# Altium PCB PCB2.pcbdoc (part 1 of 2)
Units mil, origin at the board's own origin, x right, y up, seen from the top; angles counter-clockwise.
Board outline 1825.45 x 2756.54 mil, 4 copper layers (Top Layer, 3.3V, GND, Bottom Layer); 87 components, 95 nets, 418 pads, 113 vias.
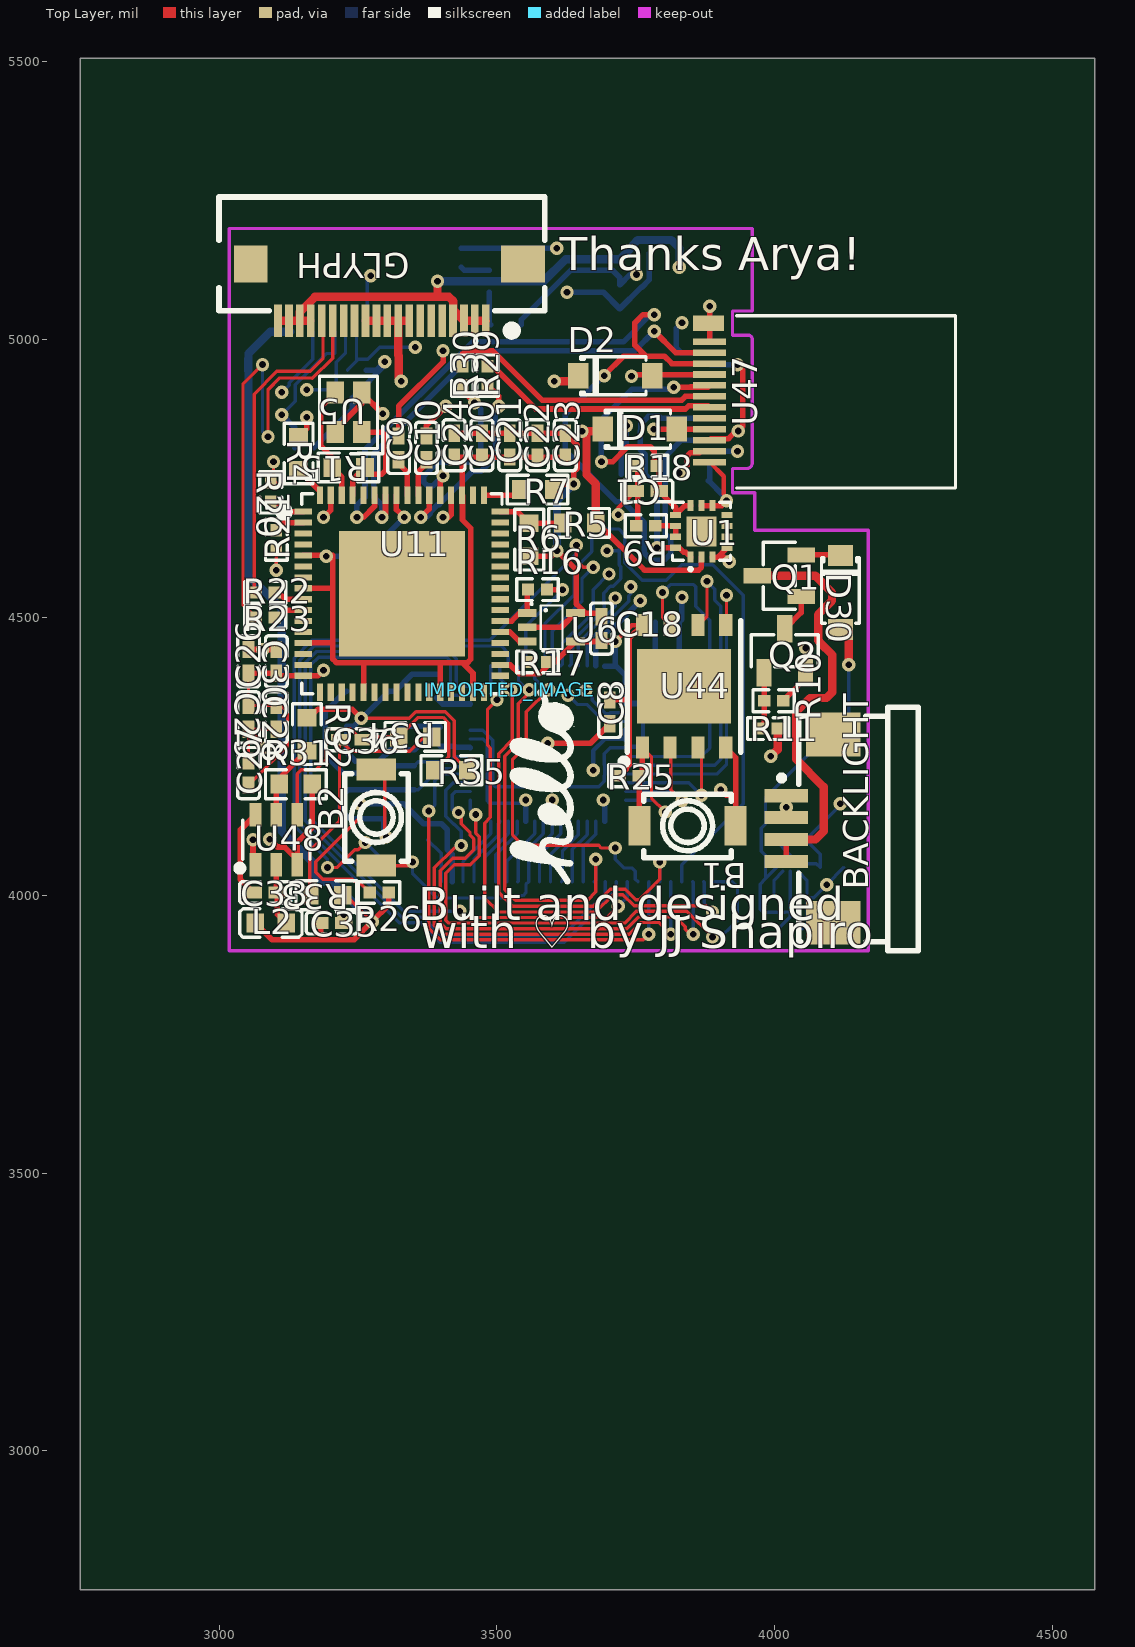
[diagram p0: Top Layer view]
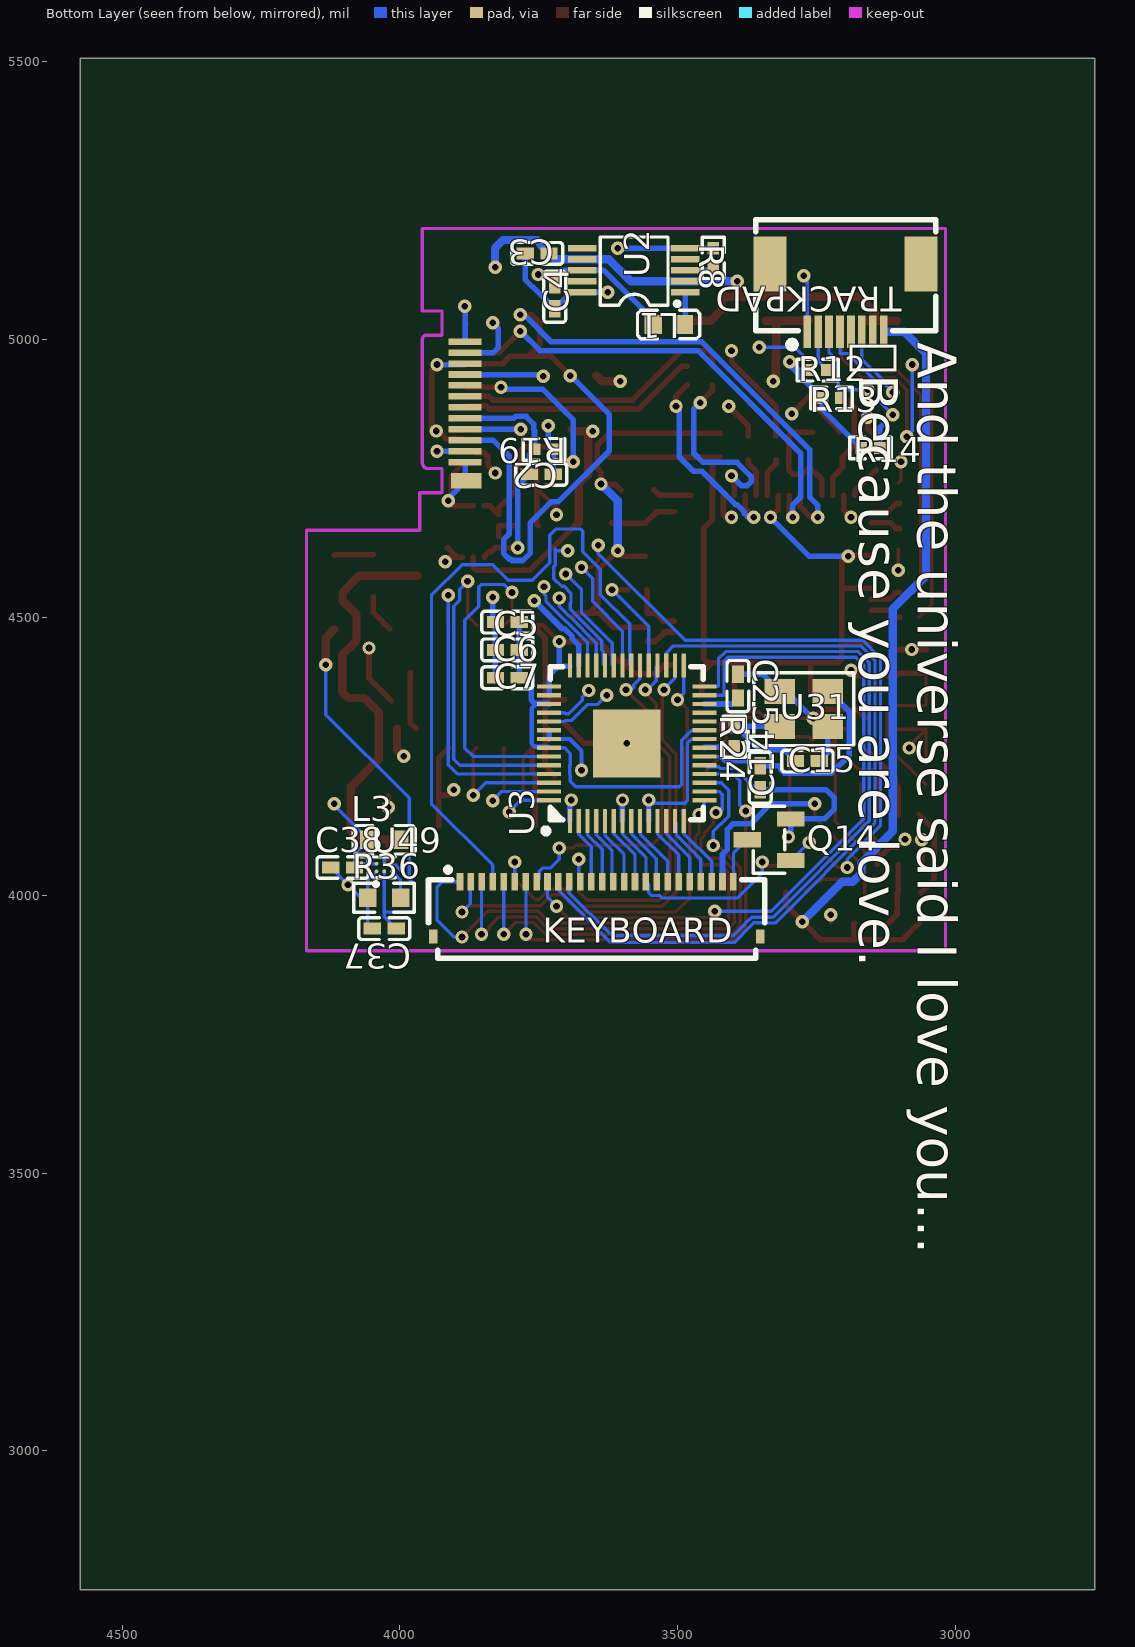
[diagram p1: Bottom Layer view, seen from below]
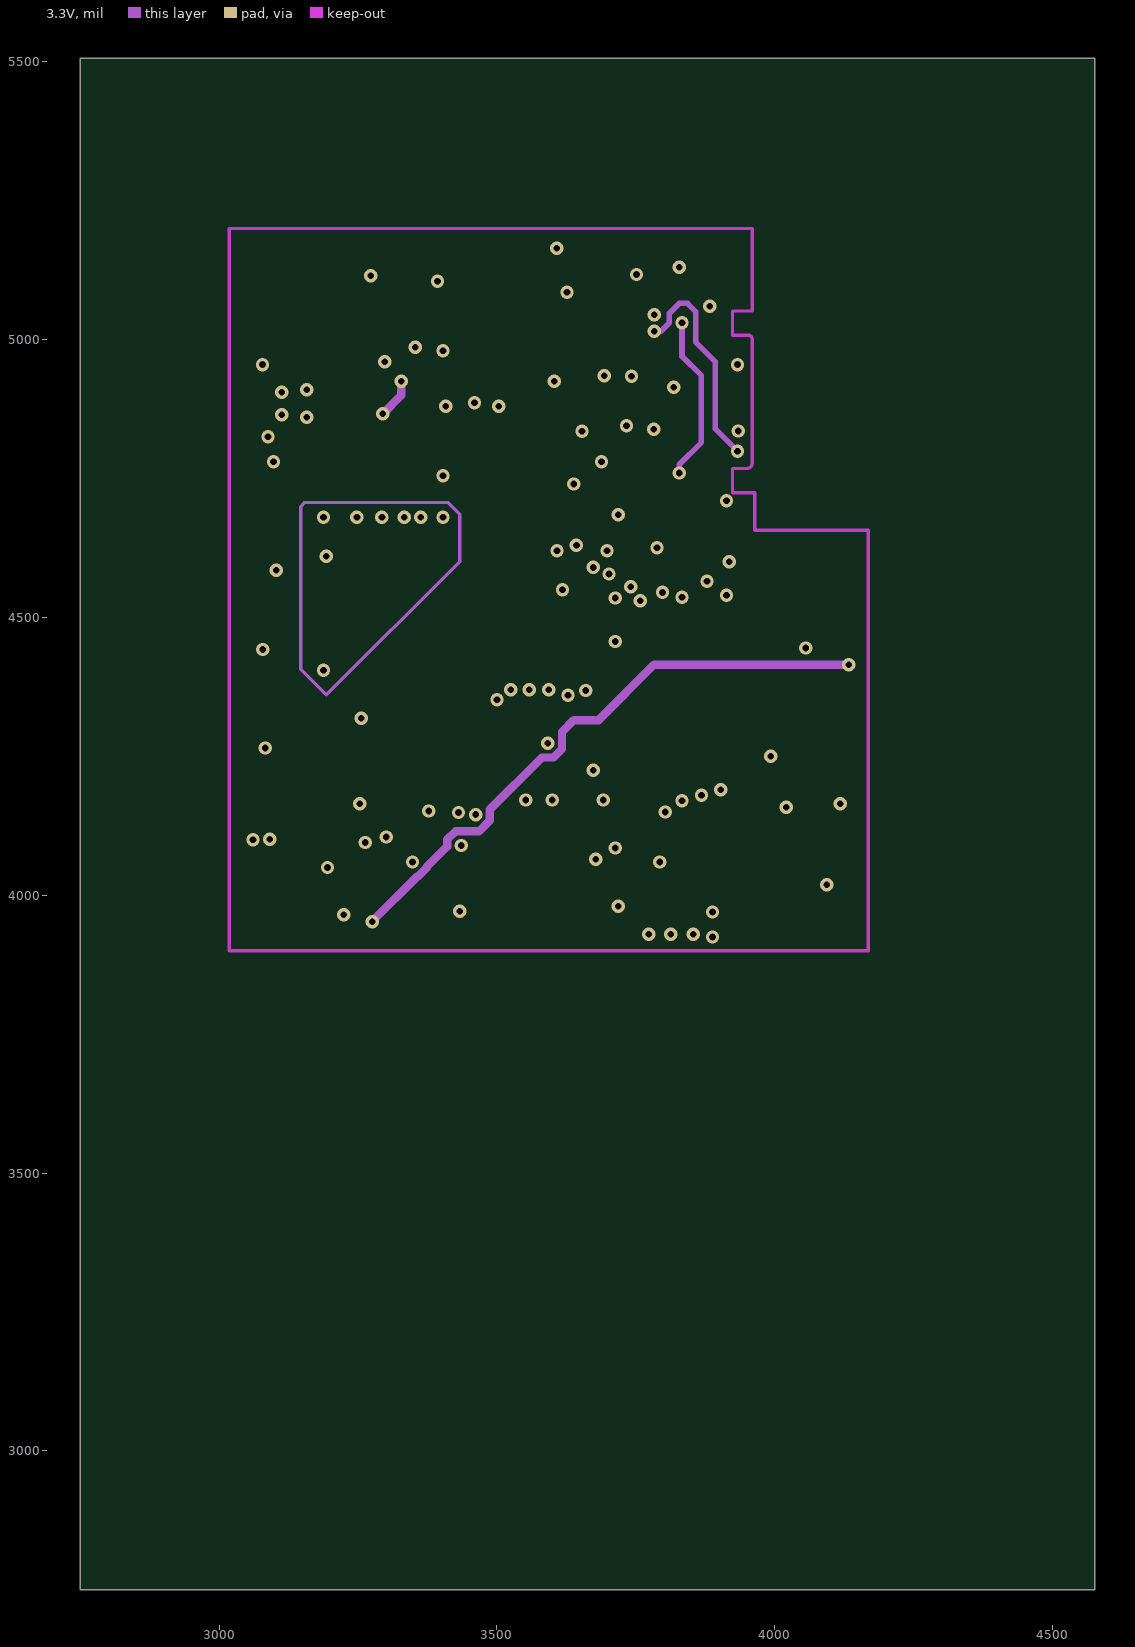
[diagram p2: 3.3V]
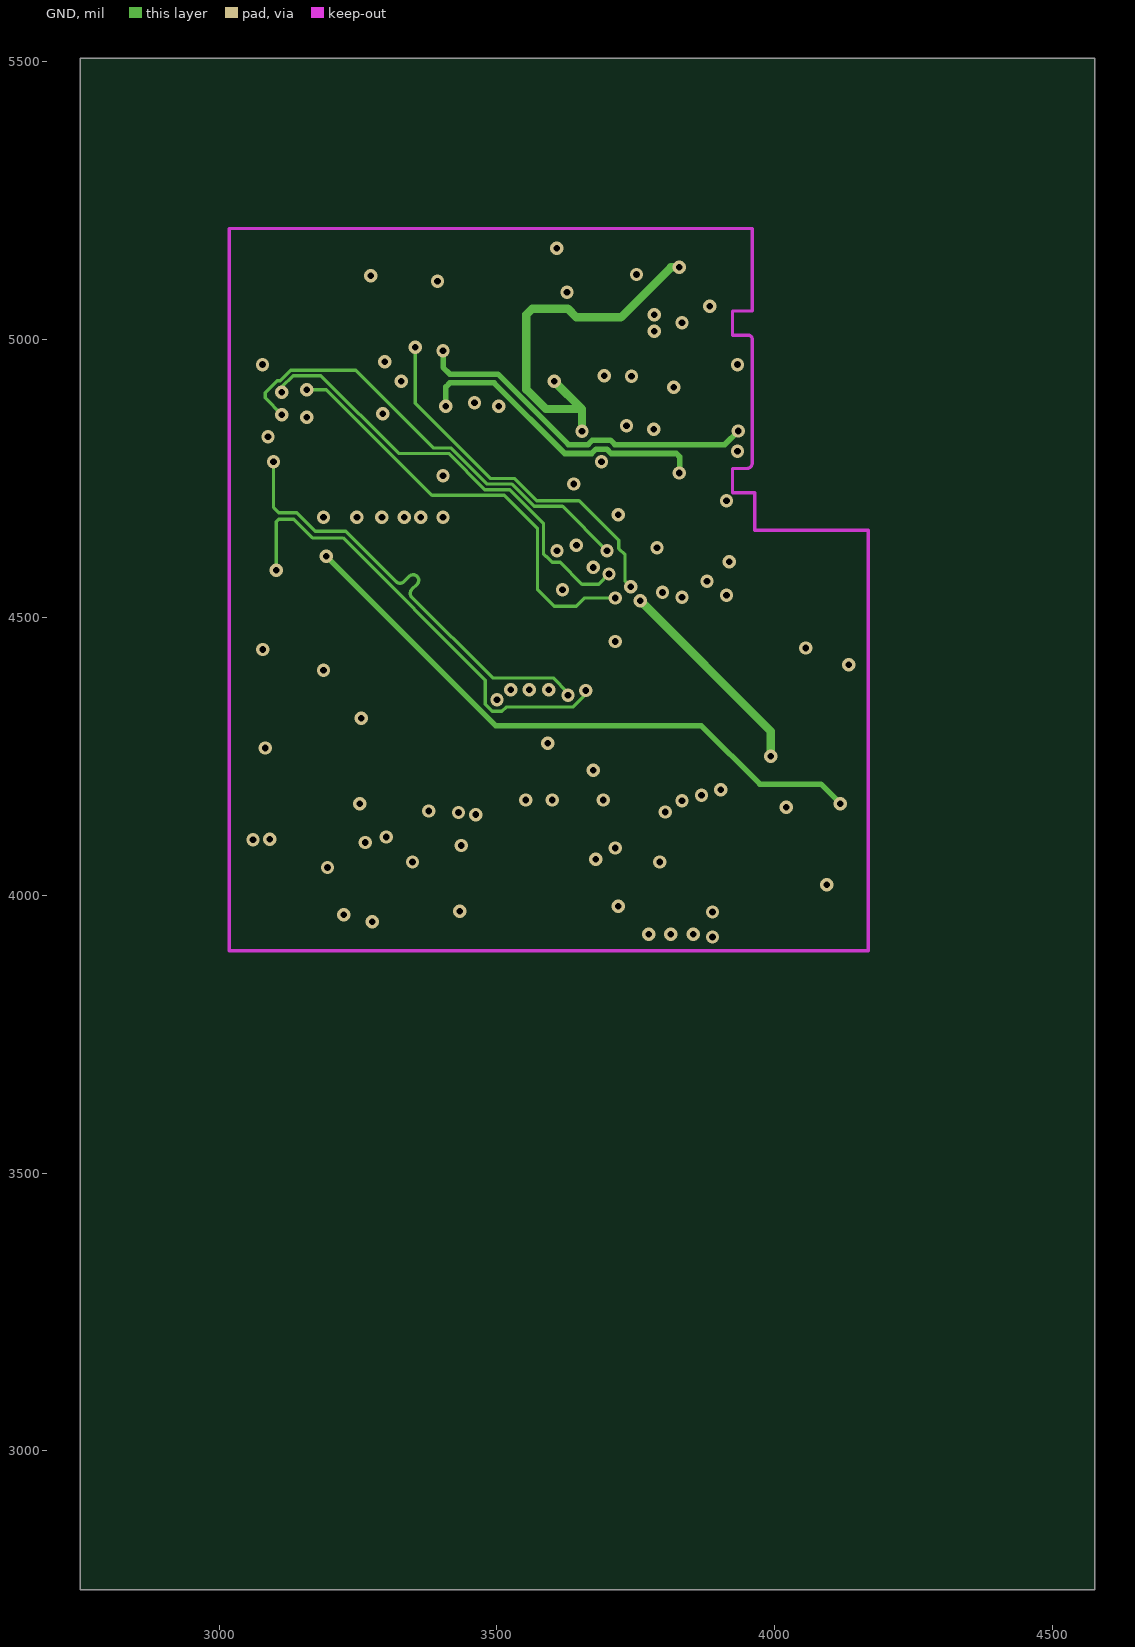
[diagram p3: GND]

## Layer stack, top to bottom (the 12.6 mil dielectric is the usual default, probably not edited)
Top Layer: signal copper (thickness not stored)
Dielectric: dielectric 12.6, FR-4, Dk 4.8
3.3V: signal copper (thickness not stored)
Dielectric: dielectric 12.6, FR-4, Dk 4.8
GND: signal copper (thickness not stored)
Dielectric: dielectric 12.6, FR-4, Dk 4.8
Bottom Layer: signal copper (thickness not stored)

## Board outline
4575.45,2750 2750,2750 2750,5506.54 4575.45,5506.54

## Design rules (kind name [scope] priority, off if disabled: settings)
BoardOutlineClearance copperThickness1oz [All] p0: genericclearance=10 ignorepadtopadclearanceinfootprint=FALSE except(0: Arc-SplitContinuation Track-SplitContinuation SMDPad-SplitContinuation THPad-SplitContinuation Via-SplitContinuation Fill-SplitContinuation Poly-SplitContinuation Region-SplitContinuation Text-SplitContinuation; 6: Track-CutoutEdge SMDPad-CutoutEdge THPad-CutoutEdge Via-CutoutEdge Region-CutoutEdge; 11.8: Track-OutlineEdge SMDPad-OutlineEdge THPad-OutlineEdge Via-OutlineEdge Fill-OutlineEdge Region-OutlineEdge Poly-OutlineEdge Text-OutlineEdge Fill-CutoutEdge)
BoardOutlineClearance copperThickness2oz [All] p0: genericclearance=10 ignorepadtopadclearanceinfootprint=FALSE except(0: Arc-SplitContinuation Track-SplitContinuation SMDPad-SplitContinuation THPad-SplitContinuation Via-SplitContinuation Fill-SplitContinuation Poly-SplitContinuation Region-SplitContinuation Text-SplitContinuation; 6: Track-CutoutEdge SMDPad-CutoutEdge THPad-CutoutEdge Via-CutoutEdge Region-CutoutEdge; 11.8: Track-OutlineEdge SMDPad-OutlineEdge THPad-OutlineEdge Via-OutlineEdge Fill-OutlineEdge Region-OutlineEdge Poly-OutlineEdge Text-OutlineEdge Fill-CutoutEdge)
Clearance copperThickness1oz [(InNet('GND') OR InNet('QSPI_SS') OR InNet('KBRD19') OR InNet('BACKLIGHT+') OR InNet('CC1') OR InNet('CC2') OR InNet('VBUS') OR InNet('+3.3V') OR InNet('$1N20') OR InNet('$1N39') OR InNet('SSTXN1') OR InNet('$1N41') OR InNet('SSTXP1') OR InNet('$1N24') OR InNet('$1N25') OR InNet('1.1V') OR InNet('$1N47') OR InNet('$1N84') OR InNet('$1N83') OR InNet('+5V') OR InNet('$1N2257') OR InNet('EINK_OLED_USB_M') OR InNet('EINK_OLED_USB_P') OR InNet('KBRD0') OR InNet('KBRD1') OR InNet('KBRD2') OR InNet('KBRD3') OR InNet('KBRD4') OR InNet('KBRD5') OR InNet('KBRD6') OR InNet('KBRD7') OR InNet('KBRD8') OR InNet('KBRD9') OR InNet('KBRD10') OR InNet('KBRD11') OR InNet('KBRD12') OR InNet('KBRD13') OR InNet('KBRD14') OR InNet('KBRD15') OR InNet('KBRD16') OR InNet('KBRD18') OR InNet('KBRD17') OR InNet('KBRD20') OR InNet('KBRD21') OR InNet('KBRD22') OR InNet('KBRD23') OR InNet('$1N22') OR InNet('CAPS-') OR InNet('$1N10') OR InNet('$1N27') OR InNet('$1N26') OR InNet('$1N19') OR InNet('$1N2') OR InNet('$1N1') OR InNet('$1N2142') OR InNet('$1N14') OR InNet('$1N15') OR InNet('KBRD_CTRL') OR InNet('TOUCHPAD_INT') OR InNet('TOUCHPAD_SCL') OR InNet('TOUCHPAD_SDA') OR InNet('$1N37') OR InNet('$1N36') OR InNet('$1N73') OR InNet('$1N72') OR InNet('$1N2151') OR InNet('KBRDUSB_P') OR InNet('$1N2152') OR InNet('KBRDUSB_M') OR InNet('$1N2157') OR InNet('$1N2158') OR InNet('$1N2308') OR InNet('TOUCHPAD_ID') OR InNet('INT_USBC_CTRL') OR InNet('SCL_USBC_CTRL') OR InNet('SDA_USBC_CTRL') OR InNet('QSPI_SD3') OR InNet('QSPI_SCLK') OR InNet('QSPI_SD0') OR InNet('QSPI_SD2') OR InNet('QSPI_SD1') OR InNet('SSRXN1') OR InNet('SSRXP1') OR InNet('USB_UP-') OR InNet('USB_UP+') OR InNet('$1N27720') OR InNet('$1N27715') OR InNet('$1N27575') OR InNet('$1N49028') OR InNet('$1N49024') OR InNet('$1N49243') OR InNet('$1N49255') OR InNet('$1N48925') OR InNet('$1N58950') OR InNet('$1N59042'))] p1: gap=7 ignorepadtopadclearanceinfootprint=FALSE except(4: Track-Track; 6: Track-SMDPad SMDPad-SMDPad Track-THPad SMDPad-THPad THPad-THPad Track-Via SMDPad-Via THPad-Via Via-Via SMDPad-Fill THPad-Fill Via-Fill Fill-Fill Track-Region SMDPad-Region THPad-Region Via-Region Region-Region Track-Poly SMDPad-Poly THPad-Poly Via-Poly Fill-Poly Region-Poly Poly-Poly Track-Text SMDPad-Text THPad-Text Via-Text Fill-Text Region-Text Poly-Text Text-Text; 6.9: Track-Hole SMDPad-Hole THPad-Hole Via-Hole Fill-Hole Region-Hole Poly-Hole Text-Hole Sheet-Hole; 11.8: Track-Fill Fill-Region Track-Sheet SMDPad-Sheet THPad-Sheet Via-Sheet Fill-Sheet Region-Sheet Poly-Sheet Text-Sheet)
Clearance copperThickness2oz [All] p1: gap=7 ignorepadtopadclearanceinfootprint=FALSE except(6: Track-SMDPad SMDPad-SMDPad Track-THPad SMDPad-THPad THPad-THPad Track-Via SMDPad-Via THPad-Via Via-Via SMDPad-Fill THPad-Fill Via-Fill Fill-Fill Track-Region SMDPad-Region THPad-Region Via-Region Region-Region Track-Poly SMDPad-Poly THPad-Poly Via-Poly Fill-Poly Region-Poly Poly-Poly Track-Text SMDPad-Text THPad-Text Via-Text Fill-Text Region-Text Poly-Text Text-Text; 6.9: Track-Hole SMDPad-Hole THPad-Hole Via-Hole Fill-Hole Region-Hole Poly-Hole Text-Hole Sheet-Hole; 8: Track-Track; 11.8: Track-Fill Fill-Region Track-Sheet SMDPad-Sheet THPad-Sheet Via-Sheet Fill-Sheet Region-Sheet Poly-Sheet Text-Sheet)
DiffPairsRouting differentialPair [All] p1: maxuncoupledlength=10 minlimit=6 maxlimit=6 mostfreqgap=6 toplayer_minwidth=5 toplayer_prefwidth=10 toplayer_maxwidth=100 bottomlayer_minwidth=5 bottomlayer_prefwidth=10 bottomlayer_maxwidth=100 midlayer1_minwidth=5 midlayer1_prefwidth=10 midlayer1_maxwidth=100 midlayer2_minwidth=5 midlayer2_prefwidth=10 midlayer2_maxwidth=100
PasteMaskExpansion pasteMaskExpansion [All] p1: expansion=0
PlaneConnect innerPlane [All] p1: planeconnectstyle=Relief reliefexpansion=20 reliefentries=4 reliefconductorwidth=10 reliefairgap=10
PolygonConnect copperRegion [All] p1: connectstyle=Relief reliefentries=4 reliefconductorwidth=10 polygonreliefangle="90 Angle" airgapwidth=10
RoutingVias viaSize [All] p1: viastyle="Through Hole" holewidth=12.0078 minholewidth=11.811 maxholewidth=248.0314 width=24.0158 minwidth=19.685 maxwidth=393.7008
SolderMaskExpansion solderMaskExpansion [All] p1: useseparateexpansions=TRUE expansion=2 expansionbottom=2
Width copperThickness1oz [All] p1: maxlimit=100 minlimit=5 preferedwidth=10
Width copperThickness2oz [All] p1: maxlimit=100 minlimit=8 preferedwidth=10

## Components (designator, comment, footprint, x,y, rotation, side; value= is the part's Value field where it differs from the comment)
B1 "BUTTON" SW-SMD_L3.9-W2.9-LS4.9-L 3843.15,4125 r180 top
B2 "BUTTON" SW-SMD_L3.9-W2.9-LS4.9-L 3283.15,4140 r90 top
BACKLIGHT "FPC-1.0-4P" FPC-SMD_4P-P1.00_HDGC_1.0K-ES-4PWB 4063.15,4120 r90 top
C1 "400pF" C0402 3770.65,4727.5 r180 top
C2 "400pF" C0402 3745.65,4757.5 r0 bottom
C3 "1uF" C0402 3753.15,5155 r180 bottom
C4 "10uF" C0402 3721.17,5076.98 r270 bottom
C5 "470nF" C0402 3806.61,4491.53 r180 bottom
C6 "470nF" C0402 3806.61,4441.53 r180 bottom
C7 "470nF" C0402 3806.61,4391.53 r180 bottom
C8 "0.1uF" C0402 3703.15,4330 r90 top
C9 "0.1uF" C0402 3323.15,4805 r90 top
C10 "0.1uF" C0402 3373.15,4805 r90 top
C14 "15pF" C0402 3351.61,4211.53 r270 bottom
C15 "15pF" C0402 3266.61,4241.53 r180 bottom
C18 "0.1uF" C0402 3688.15,4480 r270 top
C20 "0.1uF" C0402 3473.15,4810 r90 top
C21 "0.1uF" C0402 3523.15,4810 r90 top
C22 "0.1uF" C0402 3573.15,4810 r90 top
C23 "0.1uF" C0402 3623.15,4810 r90 top
C24 "10uF" C0402 3423.15,4810 r90 top
C25 "0.1uF" C0402 3391.61,4376.53 r270 bottom
C26 "10uF" C0402 3103.15,4420.81 r90 top
C27 "0.1uF" C0402 3053.15,4220 r90 top
C28 "0.1uF" C0402 3103.15,4320 r270 top
C29 "0.1uF" C0402 3053.15,4320 r270 top
C30 "0.1uF" C0402 3053.15,4420.81 r90 top
C33 "0.1uF" C0402 3083.15,4005 r180 top
C35 "10uF" C0402 3203.15,3950 r0 top
C36 "75pF" C0402 3238.15,4280 r0 top
C37 "4.7uF" C0402 4028.15,3940 r0 bottom
C38 "10uF" C0402 4103.15,4050 r180 bottom
D1 "1N4007W" SOD-123_L2.8-W1.8-LS3.7-RD 3757.18,4838.79 r0 top
D2 "1N4007W" SOD-123_L2.8-W1.8-LS3.7-RD 3713.15,4935 r0 top
D30 "1N4007W" SOD-123_L2.8-W1.8-LS3.7-RD 4118.15,4545 r270 top
GLYPH "HC-FPC-0.5-20P-FH20" FPC-SMD_20P-P0.50_HC-FPC-0.5-20P-FH20 3293.15,5085 r180 top
IMPORTED_IMAGE "IMPORTED_IMAGE" IMPORTED_IMAGE 3523.15,4370 r0 top
KEYBOARD "046809626210846+" FPC-SMD_26P-P0.50_046809626210846 3645.75,3975 r180 bottom
L1 "47uH" L0603 3516.17,5026.98 r0 bottom
L2 "47uH" L0603 3093.15,3950 r0 top
L3 "47uH" L0603 4028.15,4100 r180 bottom
Q1 "CJ2305" SOT-23-3_L2.9-W1.3-P1.90-LS2.4-BR 4008.15,4575 r0 top
Q2 "BC817" SOT-23-3_L2.9-W1.3-P1.90-LS2.4-BR 4018.15,4440 r270 top
Q14 "BC817" SOT-23-3_L2.9-W1.3-P1.90-LS2.4-BR 3335.75,4100 r180 bottom
R4 "9.53k±1%" R0603 3143.15,4795 r270 top
R5 "90.9k±1%" R0603 3648.15,4670 r180 top
R6 "10k±1%" R0603 3558.15,4640 r270 top
R7 "90.9k±1%" R0603 3573.15,4730 r180 top
R8 "56.2k" R0402 3436.17,5146.98 r270 bottom
R9 "5.1k" R0402 3768.15,4665 r180 top
R10 "5.1k" R0402 3998.15,4350 r180 top
R11 "1k" R0402 3988.15,4300 r180 top
R12 "4.7k - 0603" R0402 3248.15,4945 r180 bottom
R13 "4.7k - 0603" R0402 3223.15,4895 r180 bottom
R14 "4.7k" R0402 3153.15,4805 r180 bottom
R15 "1M" R0603 3233.15,4770 r0 top
R16 "4.7k" R0402 3573.15,4550 r0 top
R17 "4.7k" R0402 3573.15,4420 r0 top
R18 "5.1k" R0402 3770.65,4772.5 r0 top
R19 "5.1k" R0402 3740.65,4802.5 r0 bottom
R20 "22" R0402 3093.15,4725 r270 top
R21 "22" R0402 3103.15,4640 r90 top
R22 "22" R0402 3083.15,4545 r0 top
R23 "22" R0402 3083.15,4500 r0 top
R24 "1k" R0402 3398.22,4285.3 r270 bottom
R25 "5.1k" R0402 3738.15,4215 r0 top
R26 "1k" R0402 3288.15,4005 r0 top
R29 "22" R0402 3483.15,4935 r90 top
R30 "22" R0402 3438.15,4935 r90 top
R31 "511k" R0603 3138.15,4200 r0 top
R32 "511k" R0603 3158.15,4290 r270 top
R33 "49.9k" R0603 3193.15,4000 r180 top
R34 "100k" R0603 3353.15,4285 r180 top
R35 "13.3k" R0603 3418.15,4225 r0 top
R36 "36.5" R0603 4028.39,3995.62 r180 bottom
TRACKPAD "TEMPORARY 8-PIN CONN" CONN-SMD_8P-P0.50_HC-FPC-0.5-8P-FHH20 3198.15,5075 r0 bottom
U1 "FUSB302BVMPX" MLP-14_L2.5-W2.5-P0.50-BL-EP 3868.15,4655 r0 top
U2 "LM5165YQDGSRQ1" VSSOP-10_L3.0-W3.0-P0.50-LS4.9-BL 3579.09,5124.61 r90 bottom
U3 "RP2040" LQFN-56_L7.0-W7.0-P0.4-EP 3591.57,4273.38 r90 bottom
U5 "24MHz" OSC-SMD_4P-XRCGB24M000F0L00R0 3233.04,4869 r90 top
U6 "24LC02BT-I/LT" SC-70-5_L2.0-W1.3-P0.65-LS2.1-BR 3598.18,4482.27 r180 top
U11 "TUSB8044ARGCT" VQFN-64_L9.0-W9.0-P0.50-TL-EP5.8 3329.12,4542.65 r0 top
U31 "ABM8-272-T3" CRYSTAL-SMD_4P-L3.2-W2.5-BL-2 3273.22,4335.3 r180 bottom
U44 "W25Q128JVPIM" WSON-8_L5.0-W6.0-P1.27-BL-EP 3836.81,4375.89 r0 top
U47 "TYPE-C 24P-GTJB 040" USB-C-SMD_TYPE-C-24P-GTJB-040 3881.75,4887.9 r90 top
U48 "TPS54302DDCR_C311983" SOT-23-6_L2.9-W1.6-P0.95-LS2.8-BL 3103.15,4100 r0 top
U49 "TPS62801YKAT" DSBGA-6_L1.0-W0.7-R2-C3-P0.35-BL 4028.15,4050 r180 bottom

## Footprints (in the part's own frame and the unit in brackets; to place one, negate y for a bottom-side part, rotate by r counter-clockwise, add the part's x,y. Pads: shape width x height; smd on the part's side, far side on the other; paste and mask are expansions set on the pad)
C0402 [mm]
  rect 0.79x0.54 smd: 1(0.545,0) 2(-0.545,0)
  silkscreen extent -1.17,-0.5 1.17,0.5
CONN-SMD_8P-P0.50_HC-FPC-0.5-8P-FHH20 [mm]
  rect 0.35x1.5 smd: 1(1.75,1.55) 2(1.25,1.55) 3(0.75,1.55) 4(0.25,1.55) 5(-0.25,1.55) 6(-0.75,1.55) 7(-1.25,1.55) 8(-1.75,1.55)
  rect 1.5x2.5 smd: 9(-3.45,-1.55) 10(3.45,-1.55)
  silkscreen extent -4.12,-3.58 4.09,2.44
CRYSTAL-SMD_4P-L3.2-W2.5-BL-2 [mm]
  rect 1.4x1.15 smd: 1(-1.1,-0.8) 2(1.1,-0.8) 3(1.1,0.8) 4(-1.1,0.8)
  silkscreen extent -2.54,-1.9 2.29,1.65
DSBGA-6_L1.0-W0.7-R2-C3-P0.35-BL [mm]
  round 0.17 smd: A1(-0.35,-0.175) A2(-0.35,0.175) B1(0,-0.175) B2(0,0.175) C1(0.35,-0.175) C2(0.35,0.175)
  silkscreen extent -0.5,-0.85 0.5,0.48
FPC-SMD_4P-P1.00_HDGC_1.0K-ES-4PWB [mm]
  rect 0.6x2 smd: 1(1.5,1.075) 2(0.5,1.075) 3(-0.5,1.075) 4(-1.5,1.075)
  rect 2x2.5 smd: 5(-4.3,-1.075) 6(4.3,-1.075)
  silkscreen extent -5.59,-4.95 5.55,1.42
FPC-SMD_20P-P0.50_HC-FPC-0.5-20P-FH20 [mm]
  rect 0.35x1.5 smd: 1(-4.75,1.3) 2(-4.25,1.3) 3(-3.75,1.3) 4(-3.25,1.3) 5(-2.75,1.3) 6(-2.25,1.3) 7(-1.75,1.3) 8(-1.25,1.3) 9(-0.75,1.3) 10(-0.25,1.3) 11(0.25,1.3) 12(0.75,1.3) 13(1.25,1.3) 14(1.75,1.3) 15(2.25,1.3) 16(2.75,1.3) 17(3.25,1.3) 18(3.75,1.3) 19(4.25,1.3) 20(4.75,1.3)
  rect 1.542x1.7 smd: 21(5.992,-1.3)
  rect 2x1.7 smd: 22(-6.45,-1.3)
  silkscreen extent -7.45,-4.36 7.45,2.16
FPC-SMD_26P-P0.50_046809626210846 [mm]
  rect 0.3x0.8 smd: 1(-6.25,1.25) 2(-5.75,1.25) 3(-5.25,1.25) 4(-4.75,1.25) 5(-4.25,1.25) 6(-3.75,1.25) 7(-3.25,1.25) 8(-2.75,1.25) 9(-2.25,1.25) 10(-1.75,1.25) 11(-1.25,1.25) 12(-0.75,1.25) 13(-0.25,1.25) 14(0.25,1.25) 15(0.75,1.25) 16(1.25,1.25) 17(1.75,1.25) 18(2.25,1.25) 19(2.75,1.25) 20(3.25,1.25) 21(3.75,1.25) 22(4.25,1.25) 23(4.75,1.25) 24(5.25,1.25) 25(5.75,1.25) 26(6.25,1.25)
  rect 0.4x0.635 smd: 27(7.475,-1.25) 28(-7.475,-1.25)
  silkscreen extent -7.69,-2.25 7.69,2.03
IMPORTED_IMAGE [mil]
  silkscreen extent 0,-350 116,0
L0603 [mm]
  rect 0.8x0.864 smd: 1(-0.7,0) 2(0.7,0)
  silkscreen extent -1.42,-0.65 1.42,0.65
LQFN-56_L7.0-W7.0-P0.4-EP [mm]
  rect 1.1x0.2 smd: 1(-3.55,2.6) 2(-3.55,2.2) 3(-3.55,1.8) 4(-3.55,1.4) 5(-3.55,1) 6(-3.55,0.6) 7(-3.55,0.2) 8(-3.55,-0.2) 9(-3.55,-0.6) 10(-3.55,-1) 11(-3.55,-1.4) 12(-3.55,-1.8) 13(-3.55,-2.2) 14(-3.55,-2.6) 29(3.55,-2.6) 30(3.55,-2.2) 31(3.55,-1.8) 32(3.55,-1.4) 33(3.55,-1) 34(3.55,-0.6) 35(3.55,-0.2) 36(3.55,0.2) 37(3.55,0.6) 38(3.55,1) 39(3.55,1.4) 40(3.55,1.8) 41(3.55,2.2) 42(3.55,2.6)
  rect 0.2x1.1 smd: 15(-2.6,-3.55) 16(-2.2,-3.55) 17(-1.8,-3.55) 18(-1.4,-3.55) 19(-1,-3.55) 20(-0.6,-3.55) 21(-0.2,-3.55) 22(0.2,-3.55) 23(0.6,-3.55) 24(1,-3.55) 25(1.4,-3.55) 26(1.8,-3.55) 27(2.2,-3.55) 28(2.6,-3.55) 43(2.6,3.55) 44(2.2,3.55) 45(1.8,3.55) 46(1.4,3.55) 47(1,3.55) 48(0.6,3.55) 49(0.2,3.55) 50(-0.2,3.55) 51(-0.6,3.55) 52(-1,3.55) 53(-1.4,3.55) 54(-1.8,3.55) 55(-2.2,3.55) 56(-2.6,3.55)
  rect 3.1x3.1 smd: 57(0,0)
  silkscreen extent -4.13,-3.5 3.5,3.83
MLP-14_L2.5-W2.5-P0.50-BL-EP [mm]
  rect 0.28x0.505 smd: 1(-0.5,-1.178) 2(0,-1.178) 3(0.5,-1.178) 8(0.5,1.178) 9(0,1.178) 10(-0.5,1.178)
  rect 0.505x0.28 smd: 4(1.178,-0.75) 5(1.178,-0.25) 6(1.178,0.25) 7(1.178,0.75) 11(-1.178,0.75) 12(-1.178,0.25) 13(-1.178,-0.25) 14(-1.178,-0.75)
  rect 1.375x1.375 smd: 15(0,0)
  silkscreen extent -1.33,-1.8 1.33,1.33
OSC-SMD_4P-XRCGB24M000F0L00R0 [mm]
  rect 1x0.8 smd: 1(-0.9,-0.6) 2(0.9,-0.6) 3(0.9,0.6) 4(-0.9,0.6)
  silkscreen extent -1.89,-1.56 1.65,1.33
R0402 [mm]
  rect 0.566x0.54 smd: 1(-0.433,0) 2(0.433,0)
  silkscreen extent -0.94,-0.5 0.94,0.5
R0603 [mil]
  rect 31.75x34.02 smd: 1(-29.66,0) 2(29.66,0)
  silkscreen extent -55,-26 55,26
SC-70-5_L2.0-W1.3-P0.65-LS2.1-BR [mm]
  rect 0.85x0.35 smd: 1(1.1,-0.65) 2(1.1,0) 3(1.1,0.65) 4(-1.1,0.65) 5(-1.1,-0.65)
  silkscreen extent -0.5,-1.12 0.96,1
SOD-123_L2.8-W1.8-LS3.7-RD [mm]
  rect 0.95x1.15 smd: 1(-1.692,0) 2(1.692,0)
  silkscreen extent -1.58,-0.87 1.41,0.87
SOT-23-3_L2.9-W1.3-P1.90-LS2.4-BR [mm]
  rect 1.25x0.7 smd: 1(1,-0.95) 2(1,0.95) 3(-1,0)
  silkscreen extent -0.73,-1.53 0.73,1.53
SOT-23-6_L2.9-W1.6-P0.95-LS2.8-BL [mil]
  rect 20.95x42.2 smd: 1(-37.4,-45.24) 2(0,-45.24) 3(37.4,-45.24) 4(37.4,45.24) 5(0,45.24) 6(-37.4,45.24)
  silkscreen extent -72,-57 61,35
SW-SMD_L3.9-W2.9-LS4.9-L [mm]
  rect 1x1.8 smd: 1(-2.2,0) 2(2.2,0)
  silkscreen extent -2,-1.45 2,1.45
USB-C-SMD_TYPE-C-24P-GTJB-040 [mm]
  rect 0.7x1.4 smd: 25(3.6,0.025)
  rect 0.7x1.4 smd far side: 26(-3.6,0.025)
  rect 0.3x1.5 smd: A1(2.75,-0.025) A2(2.25,-0.025) A3(1.75,-0.025) A4(1.25,-0.025) A5(0.75,-0.025) A6(0.25,-0.025) A7(-0.25,-0.025) A8(-0.75,-0.025) A9(-1.25,-0.025) A10(-1.75,-0.025) A11(-2.25,-0.025) A12(-2.75,-0.025)
  rect 0.3x1.5 smd far side: B1(-2.75,-0.025) B2(-2.25,-0.025) B3(-1.75,-0.025) B4(-1.25,-0.025) B5(-0.75,-0.025) B6(-0.25,-0.025) B7(0.25,-0.025) B8(0.75,-0.025) B9(1.25,-0.025) B10(1.75,-0.025) B11(2.25,-0.025) B12(2.75,-0.025)
  Board Outline Layer lines w0.15: -4.15,-1.075 -3.05,-1.075 ; -4.15,-1.075 -4.15,-1.975 -4.15,-1.075 ; -4.15,-1.075 -3.05,-1.075 ; -3.05,-1.075 -3.05,-1.7 ; -3.05,-1.075 -3.05,-1.7 ; 3.05,-1.075 3.05,-1.785 ; 3.05,-1.075 4.15,-1.075 ; 3.05,-1.075 3.05,-1.785 ; 3.05,-1.075 4.15,-1.075 ; 4.15,-1.075 4.15,-1.975 4.15,-1.075 ; -3.05,-1.7 -3.05,-1.719 ; -3.05,-1.7 -3.05,-1.719 ; -3.05,-1.719 ccw(c-2.794,-1.719) -2.794,-1.975 cw(c-2.794,-1.719) -3.05,-1.719 ; 3.05,-1.785 cw(c2.86,-1.785) 2.86,-1.975 ; 3.05,-1.785 cw(c2.86,-1.785) 2.86,-1.975 ; 2.86,-1.975 -2.741,-1.975 2.86,-1.975 ; -3.937,-1.075 cw(c-3.937,-1.077) -3.935,-1.077 ccw(c-3.937,-1.077) -3.937,-1.075
  silkscreen extent -3.94,-11.27 3.94,-1.27
VQFN-64_L9.0-W9.0-P0.50-TL-EP5.8 [mm]
  rect 0.8x0.28 smd: 1(-4.5,3.75) 2(-4.5,3.25) 3(-4.5,2.75) 4(-4.5,2.25) 5(-4.5,1.75) 6(-4.5,1.25) 7(-4.5,0.75) 8(-4.5,0.25) 9(-4.5,-0.25) 10(-4.5,-0.75) 11(-4.5,-1.25) 12(-4.5,-1.75) 13(-4.5,-2.25) 14(-4.5,-2.75) 15(-4.5,-3.25) 16(-4.5,-3.75) 33(4.5,-3.75) 34(4.5,-3.25) 35(4.5,-2.75) 36(4.5,-2.25) 37(4.5,-1.75) 38(4.5,-1.25) 39(4.5,-0.75) 40(4.5,-0.25) 41(4.5,0.25) 42(4.5,0.75) 43(4.5,1.25) 44(4.5,1.75) 45(4.5,2.25) 46(4.5,2.75) 47(4.5,3.25) 48(4.5,3.75)
  rect 0.28x0.8 smd: 17(-3.75,-4.5) 18(-3.25,-4.5) 19(-2.75,-4.5) 20(-2.25,-4.5) 21(-1.75,-4.5) 22(-1.25,-4.5) 23(-0.75,-4.5) 24(-0.25,-4.5) 25(0.25,-4.5) 26(0.75,-4.5) 27(1.25,-4.5) 28(1.75,-4.5) 29(2.25,-4.5) 30(2.75,-4.5) 31(3.25,-4.5) 32(3.75,-4.5) 49(3.75,4.5) 50(3.25,4.5) 51(2.75,4.5) 52(2.25,4.5) 53(1.75,4.5) 54(1.25,4.5) 55(0.75,4.5) 56(0.25,4.5) 57(-0.25,4.5) 58(-0.75,4.5) 59(-1.25,4.5) 60(-1.75,4.5) 61(-2.25,4.5) 62(-2.75,4.5) 63(-3.25,4.5) 64(-3.75,4.5)
  rect 5.75x5.75 smd: 65(0,0)
  silkscreen extent -5.59,-4.58 4.58,4.58
VSSOP-10_L3.0-W3.0-P0.50-LS4.9-BL [mm]
  rect 0.3x1.3 smd: 1(-1,-2.35) 2(-0.5,-2.35) 3(0,-2.35) 4(0.5,-2.35) 5(1,-2.35) 6(1,2.35) 7(0.5,2.35) 8(0,2.35) 9(-0.5,2.35) 10(-1,2.35)
  silkscreen extent -1.62,-2.08 1.52,1.54
WSON-8_L5.0-W6.0-P1.27-BL-EP [mm]
  rect 0.6x1 smd: 1(-1.905,-2.8) 2(-0.635,-2.8) 3(0.635,-2.8) 4(1.905,-2.8) 5(1.905,2.8) 6(0.635,2.8) 7(-0.635,2.8) 8(-1.905,2.8)
  rect 4.3x3.4 smd: 9(0,0)
  silkscreen extent -2.9,-3.6 2.6,3

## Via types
v1: diameter 24.02, hole 12.01, Top Layer to Bottom Layer, 113 vias

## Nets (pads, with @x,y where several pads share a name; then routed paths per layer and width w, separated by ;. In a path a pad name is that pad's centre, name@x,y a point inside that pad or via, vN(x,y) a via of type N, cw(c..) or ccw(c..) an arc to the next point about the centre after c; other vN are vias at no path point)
1.1V: C20.2 C21.2 C22.2 C23.2 C24.2 C38.1 L3.1 U11.5 U11.8 U11.13 U11.21 U11.28 U11.31 U11.51 U11.57 U49.A2 | length 2862
  Top Layer w10: U11.13@3151.96,4454.07 3203.63,4454.07 3204.95,4452.76 ; U11.8@3151.96,4552.49 3204.61,4552.49 3204.95,4552.15 ; U11.5@3151.96,4611.55 3204.95,4611.55 3204.95,4552.15 ; U11.21@3260.22,4365.48 3260.22,4416.56 3258.3,4418.48 ; U11.57@3319.28,4719.81 3319.28,4693.87 v1(3333.15,4680) ; U11.28@3398.02,4365.48 3398.4,4365.86 3398.4,4418.48 ; U11.31@3457.07,4365.48 3457.07,4399.55 3438.15,4418.48 ; C23.2@3623.15,4788.54 C22.2@3573.15,4788.54 C21.2@3523.15,4788.54 C20.2@3473.15,4788.54 C24.2@3423.15,4788.54 3437.39,4774.3 U11.51@3437.39,4719.81 3438.15,4719.05 3438.15,4675.53 3453.29,4660.39 3453.29,4424.91 3446.86,4418.48 3438.15,4418.48 ; 3204.95,4452.76 3204.95,4552.15 ; 3204.95,4452.76 3204.95,4424.91 3211.38,4418.48 3258.3,4418.48 ; 3258.3,4418.48 3398.4,4418.48 ; 3398.4,4418.48 3438.15,4418.48
  GND w10: v1(3193.15,4610) 3498.15,4305 3868.15,4305 3973.15,4200 4083.15,4200 v1(4118.15,4165)
  Bottom Layer w6: U49.A2@4041.93,4056.89 4074.8,4056.89 C38.1@4081.69,4050 4081.69,4074.03 L3.1@4055.71,4100.01 4118.15,4162.45 v1(4118.15,4165)
  Bottom Layer w10: v1(3193.15,4610) 3263.15,4610 v1(3333.15,4680)
$1N1: R5.2 R6.1 U11.48 | length 120.9
  Top Layer w10: U11.48@3506.29,4690.29 3506.58,4690 3537.81,4690 R6.1@3558.15,4669.66 3618.15,4669.66 R5.2@3618.49,4670
$1N2: R4.2 U11.64 | length 61.4
  Top Layer w10: R4.2@3143.15,4765.34 3181.48,4727.01 U11.64@3181.48,4719.81
$1N10: L1.1 U2.1 | length 59.1
  Bottom Layer w10: U2.1@3486.57,5085.24 3486.57,5029.01 L1.1@3488.61,5026.97
$1N14: R8.2 U2.3 | length 52.6
  Bottom Layer w10: R8.2@3436.17,5129.94 3441.51,5124.6 U2.3@3486.57,5124.6
$1N15: R9.1 U1.12 U1.13 | length 51.3
  Top Layer w10: R9.1@3790.19,4665 3821.63,4665 U1.12@3821.79,4664.84 U1.13@3821.79,4645.16
$1N19: Q14.1 U3.36 | length 1406.4
  Top Layer w6: v1(3195.16,4049.97) 3211.9,4049.97 3243.99,4082.06 3250.21,4082.06 v1(3263.15,4095) ; v1(3643.15,4630) 3643.15,4601.99 3655.14,4590 v1(3673.15,4590)
  Bottom Layer w6: v1(3195.16,4049.97) 3195.16,4064.95 3135.11,4125 3135.11,4426.97 3166.79,4458.65 3486.8,4458.65 3643.15,4615 v1(3643.15,4630) ; v1(3263.15,4095) 3295.55,4062.6 Q14.1@3296.38,4062.6 ; U3.36@3599.44,4413.15 3599.44,4475 3653.15,4528.7 3653.15,4570 v1(3673.15,4590)
$1N20: C5.1 C6.1 C7.1 U3.23 U3.45 U3.50 | length 724.5
  Bottom Layer w6: U3.23@3451.81,4297 3474.36,4297 3492.47,4278.89 3492.47,4200 3497.47,4195 3683.15,4195 3693.15,4205 3693.15,4215.31 3694.14,4216.3 3694.14,4233.7 3693.15,4234.69 3693.15,4255 3703.65,4265.5 U3.50@3731.33,4265.5
  Bottom Layer w8: U3.50@3731.33,4265.5 3733.16,4267.33 3757.12,4267.33 3762.97,4273.18 3762.97,4336.57 3757.54,4342.01 3757.54,4345.07
  Bottom Layer w10: U3.45@3731.33,4344.24 3732.16,4345.07 3757.54,4345.07 3763.97,4351.51 3763.97,4376.88 3778.63,4391.53 C7.1@3785.15,4391.53 C6.1@3785.15,4441.53 C5.1@3785.15,4491.53
$1N22: KEYBOARD.25 R26.1 | length 543
  Top Layer w6: v1(3253.15,4165) 3253.15,4139.69 3174.17,4060.71 3174.17,4041.27 3186.44,4029.01 3239.71,4029.01 3243.99,4024.72 3251.39,4024.72 R26.1@3271.11,4005
  Bottom Layer w10: v1(3253.15,4165) 3331.77,4165 3367.99,4128.78 3400.26,4128.78 3410.71,4118.33 3410.71,4082.61 3419.37,4073.95 KEYBOARD.25@3419.37,4024.22
$1N24: C14.2 U3.20 U31.3 | length 422.4
  Bottom Layer w6: C14.2@3351.61,4232.99 3358.62,4240 3415.08,4240 3424.84,4249.76 U3.20@3451.81,4249.76
  Bottom Layer w10: U31.3@3229.92,4366.8 3227.18,4366.8 3191.37,4331 3191.37,4251.78 3223.23,4219.92 3308.18,4219.92 3314.61,4226.35 3314.61,4232.92 3314.69,4232.99 C14.2@3351.61,4232.99
$1N25: C15.2 R24.1 U31.1 | length 217.6
  Bottom Layer w10: C15.2@3288.07,4241.53 3308.07,4261.53 3351.61,4261.53 3392.42,4302.34 R24.1@3398.22,4302.34 3396.75,4303.81 U31.1@3316.53,4303.81
$1N26: Q2.1 R10.2 R11.2 | length 104.9
  Top Layer w10: R11.2@3971.11,4300 3981.11,4310 R10.2@3981.11,4350 3981.11,4400.27 Q2.1@3980.75,4400.63
$1N27: Q1.1 Q2.3 | length 70.4
  Top Layer w10: Q2.3@4018.15,4479.37 4047.52,4508.74 Q1.1@4047.52,4537.6
$1N36: R15.1 U5.3 U11.62 | length 211.5
  Top Layer w10: U5.3@3209.42,4904.43 3182.69,4877.7 3182.69,4809.34 3203.49,4788.54 R15.1@3203.49,4770 3220.85,4752.64 U11.62@3220.85,4719.81
$1N37: R15.2 U5.1 U11.61 | length 212.7
  Top Layer w10: U11.61@3240.54,4719.81 3240.54,4747.73 R15.2@3262.81,4770 3274.88,4757.93 3293.15,4757.93 3300.22,4765 3300.22,4826.5 3293.15,4833.57 U5.1@3256.66,4833.57
$1N39: C9.2 U11.56 | length 70.3
  Top Layer w10: C9.2@3323.15,4783.54 3323.15,4776.91 3338.96,4761.1 U11.56@3338.96,4719.81
$1N41: C10.2 U11.55 | length 69.7
  Top Layer w10: U11.55@3358.65,4719.81 3358.65,4762.41 3373.15,4776.91 C10.2@3373.15,4783.54
$1N47: C25.1 U3.26 | length 64.7
  Bottom Layer w10: C25.1@3391.61,4355.07 3402.45,4344.24 U3.26@3451.81,4344.24
$1N72: R17.1 U6.3 U11.37 | length 55.6
  Top Layer w10: U11.37@3506.29,4473.75 3523.4,4473.75 3540.47,4456.68 U6.3@3554.87,4456.68
$1N73: R16.1 U6.1 U11.38 | length 97.2
  Top Layer w10: U11.38@3506.29,4493.44 3526.59,4493.44 3541.01,4507.86 U6.1@3554.87,4507.86 3554.87,4548.76 R16.1@3556.11,4550
$1N83: D2.2 U47.A4 U47.B9 | length 283.8
  Top Layer w10: v1(3742.18,4933.79) 3745.48,4937.09 U47.A4@3882.73,4937.11
  Bottom Layer w10: v1(3742.18,4933.79) 3745.48,4937.09 U47.B9@3882.73,4937.11
$1N84: D1.2 U47.A9 U47.B4 | length 201.1
  Top Layer w10: v1(3782.18,4838.66) 3782.32,4838.79 D1.2@3823.81,4838.79 3882.57,4838.79 U47.A9@3882.73,4838.69
  Bottom Layer w10: v1(3782.18,4838.66) U47.B4@3882.73,4838.69
$1N2142: R7.2 U11.49 | length 70.9
  Top Layer w10: U11.49@3476.76,4719.81 3533.3,4719.81 R7.2@3543.49,4730
$1N2151: R20.2 U11.1 | length 57.9
  Top Layer w10: R20.2@3100.19,4705 3106.82,4705 3121.53,4690.29 U11.1@3151.96,4690.29
$1N2152: R21.2 U11.2 | length 56.2
  Top Layer w10: R21.2@3100.19,4660 3106.82,4660 3117.41,4670.6 U11.2@3151.96,4670.6
$1N2157: R22.2 U11.9 | length 56.8
  Top Layer w10: R22.2@3100.19,4545 3106.82,4545 3119.01,4532.81 U11.9@3151.96,4532.81
$1N2158: R23.2 U11.10 | length 57.2
  Top Layer w10: R23.2@3100.19,4500 3106.82,4500 3119.93,4513.12 U11.10@3151.96,4513.12
$1N2257: D30.1 Q1.2 | length 70.9
  Top Layer w10: Q1.2@4047.52,4612.4 4117.38,4612.4 D30.1@4118.15,4611.63
$1N2308: R24.2 U3.21 | length 54.7
  Bottom Layer w10: R24.2@3398.22,4268.26 3423.68,4268.26 3425.61,4266.33 3450.99,4266.33 U3.21@3451.81,4265.5
$1N27575: U47.B8
$1N27715: R30.1 U11.53 | length 349.5
  Top Layer w10: U11.53@3398.02,4719.81 3398.02,4749.87 v1(3403.15,4755) ; R30.1@3438.15,4917.96 3438.15,4908.07 v1(3459.68,4886.54)
  Bottom Layer w10: v1(3403.15,4755) 3385.05,4736.91 3375.05,4736.91 3367.98,4743.98 3367.98,4753.98 3393.01,4779 3454.78,4779 3471.22,4795.44 3471.22,4875 v1(3459.68,4886.54)
$1N27720: R29.1 U11.54 | length 366.6
  Top Layer w10: v1(3363.15,4680) 3378.15,4695 3378.15,4719.63 U11.54@3378.33,4719.81 ; R29.1@3483.15,4917.96 3503.15,4897.96 v1(3503.15,4880)
  Bottom Layer w10: v1(3363.15,4680) 3373.15,4680 3380.16,4687.01 3380.16,4689.52 3393.62,4702.99 3396.14,4702.99 3456.15,4763 3471.4,4763 3497.22,4788.82 3497.22,4874.07 v1(3503.15,4880)
$1N48925: R31.1 R32.2 U48.5 | length 137.9
  Top Layer w10: U48.5@3103.15,4145.24 3103.15,4194.66 R31.1@3108.49,4200 3108.49,4210.68 R32.2@3158.15,4260.34
$1N49024: C33.1 U48.6 | length 161.4
  Top Layer w10: C33.1@3061.69,4005 3038.15,4028.54 3038.15,4117.64 U48.6@3065.75,4145.24
$1N49028: C33.2 L2.2 U48.2 | length 112
  Top Layer w10: U48.2@3103.15,4054.76 3103.15,4006.46 C33.2@3104.61,4005 3104.61,3966.11 L2.2@3120.71,3950.01
$1N49243: C36.2 R33.2 R34.1 | length 487.6
  Top Layer w6: R33.2@3163.49,4000 3163.49,4080.34 3216.69,4133.54 C36.2@3216.69,4280 3237.68,4259.01 3343.08,4259.01 3369.08,4285 R34.1@3382.81,4285
$1N49255: C36.1 R34.2 R35.1 U48.4 | length 533.7
  Top Layer w6: U48.4@3140.55,4145.24 3140.55,4218.33 3148.21,4225.99 3174.14,4225.99 3193.15,4245 3193.15,4264.65 3192.15,4265.65 3192.15,4294.35 3197.41,4299.61 3235.96,4299.61 3255.58,4280 C36.1@3259.61,4280 3264.61,4285 R34.2@3323.49,4285 3358.49,4320 3403.15,4320 3413.15,4310 3413.15,4249.66 R35.1@3388.49,4225
$1N58950: L3.2 U49.B2 | length 54.5
  Bottom Layer w6: L3.2@4000.59,4100.01 4028.15,4072.45 U49.B2@4028.15,4056.89
$1N59042: R36.2 U49.C1 | length 54
  Bottom Layer w6: R36.2@3998.73,3995.62 3998.73,4027.47 U49.C1@4014.37,4043.11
